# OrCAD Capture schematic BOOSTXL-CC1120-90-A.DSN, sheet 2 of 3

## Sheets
2 CC1190: size B
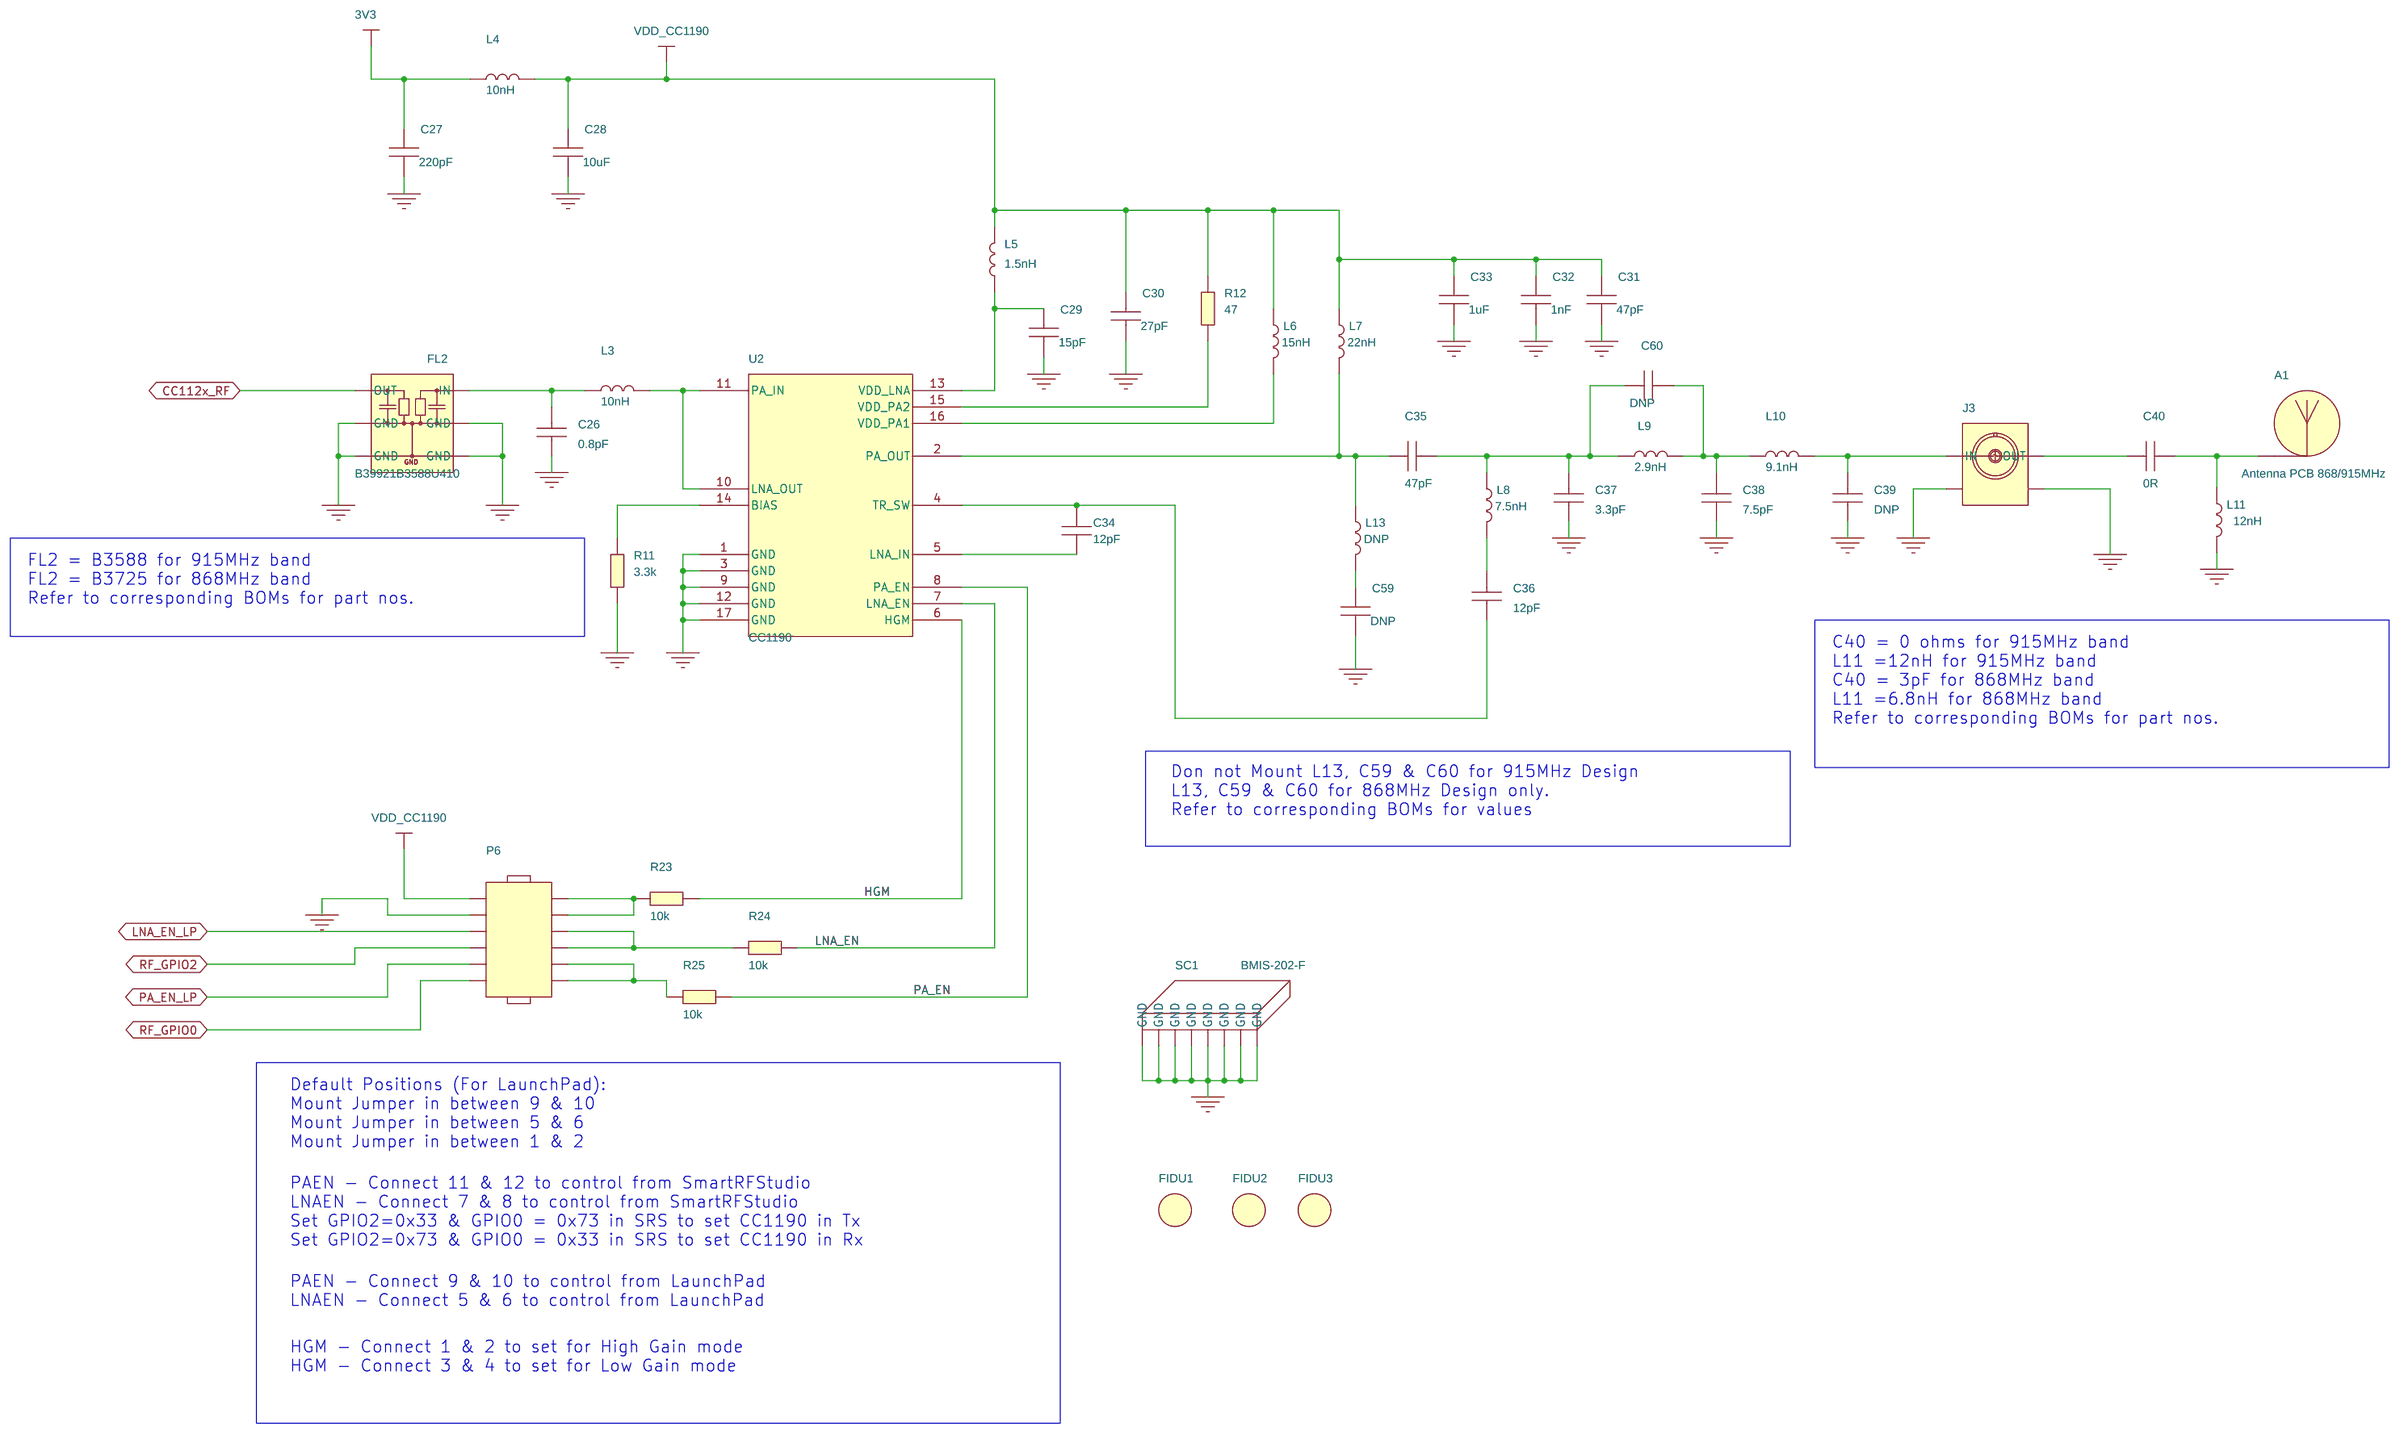
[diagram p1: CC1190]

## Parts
A1  Antenna PCB 868/915MHz  [Antenna868_915MHz_A2N]
C26  0.8pF  [CAPC1005X60N]
C27  220pF  [CAPC1005X60N]
C28  10uF  [CAPC1608X100N]
C29  15pF  [CAPC1005X60N]
C30  27pF  [CAPC1005X60N]
C31  47pF  [CAPC1005X60N]
C32  1nF  [CAPC1005X60N]
C33  1uF  [CAPC1005X60N]
C34  12pF  [CAPC1005X60N]
C35  47pF  [CAPC1005X60N]
C36  12pF  [CAPC1005X60N]
C37  3.3pF  [CAPC1005X60N]
C38  7.5pF  [CAPC1005X60N]
C39  DNP  [CAPC1005X60N]
C40  0R  [CAPC1005X60N]
C59  DNP  [CAPC1005X60N]
C60  DNP  [CAPC1005X60N]
FIDU1  FIDU_1MM  [FID100X115]
FIDU2  FIDU_1MM  [FID100X115]
FIDU3  FIDU_1MM  [FID100X115]
FL2  B39921B3588U410  [FIL_DCC6CN]
J3  1551372-1  [TE_1551372-1_A2N]
L3  10nH  [IND_LQW15AN]
L4  10nH  [IND_LQW15AN]
L5  1.5nH  [INDC1005X60N]
L6  15nH  [IND_LQW15AN]
L7  22nH  [INDC1608X100N]
L8  7.5nH  [IND_LQW15AN]
L9  2.9nH  [IND_LQW15AN]
L10  9.1nH  [INDC1005X60N]
L11  12nH  [IND_LQW15AN]
L13  DNP  [INDC1005X60N]
P6  TSM-106-01-L-DV-P  [SAMTEC_TSM10601LDVPN]
R11  3.3k  [RESC1005X40N]
R12  47  [RESC1005X40N]
R23  10k  [RESC1005X40N]
R24  10k  [RESC1005X40N]
R25  10k  [RESC1005X40N]
SC1  BMIS-202-F  [MECH_BMIS202FN]
U2  CC1190  [QFNFC65P400X400X100-17AN]

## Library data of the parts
A1 = ANTENNA_0: MECHANIC, ANTENNA PCB HELIX 868/915MHz, SMD; AutoDoc File: http://notefied-dynamic-precision.com/DB/Apps/Desktop/Item/Object.aspx?id=87165; Budget Currency: N/A; Budget Price: N/A; Datasheet URL 1: N/A; Datasheet URL 2: www.ti.com; Definied Quality: COMMERCIAL; Esd Level: N/A; FPLIST: Antenna868_915MHz_A2N,Antenna868_915MHz_MIRROR_A2N,; Frequency: 868/915MHz; Last Time Buy: N/A; Lead Time: N/A; MPN: ANTENNA PCB HELIX 868/915MHz; MPN Status: ACTIVE; MSL: N/A; MTBF: N/A; MTBF Standard: N/A; Manufacturer: TEXAS INSTRUMENTS; Max Oper Temp: N/A; Min Oper Temp: N/A; Mounting Type: SMD; NOTE Status: PREFERRED; Old Footprint: Antenna868_915MHz_A2N,Antenna868_915MHz_MIRROR_A2N; Packing Size: 2500; Packing Type: TAPE_&_REEL; Part Number: 13-00397; Part Type: MECHANIC\ANTENNA; Revision: R003; RoHS Status: ROHS_COMPLIANT; WEIGHT: N/A
C26 = CAPACITOR: CAPACITOR, CERAMIC C0G/NP0, 0.8pF, 50V, -0.1pF/+0.1pF, -55DEGC/+125DEGC, 0402, SMD; ALT_SYMBOLS: CAPC1005X60L,CAPC1005X60M; AutoDoc File: http://notefied-dynamic-precision.com/DB/Apps/Desktop/Item/Object.aspx?id=90851; Budget Currency: EUR; Budget Price: 0.014; Datasheet URL 1: http://search.murata.co.jp/Ceramy/image/img/w_hinm/L0005E.pdf; Datasheet URL 2: http://psearch.murata.com/capacitor/product/GRM1555C1HR80BA01%23.pdf; Definied Quality: INDUSTRIAL; Dielectric Type: C0G/NP0; Esd Level: N/A; FPLIST: CAPC1005X60N,CAPC1005X60L,CAPC1005X60M; Last Time Buy: N/A; Lead Time: 12; MPN: GRM1555C1HR80BA01D; MPN Status: ACTIVE; MSL: N/A; MTBF: N/A; MTBF Standard: N/A; Manufacturer: MURATA; Max Oper Temp: +125DEGC; Max TC: +30PPM/DEGC; Max Tol: +0.1pF; Min Oper Temp: -55DEGC; Min TC: -30PPM/DEGC; Min Tol: -0.1pF; Mounting Type: SMD; NOTE Status: PREFERRED; PCB Package: 0402; Packing Size: 10000; Packing Type: TAPE_&_REEL; Part Number: 02-05034; Part Type: CAPACITOR\CERAMIC\0402; Revision: R001; RoHS Status: ROHS_COMPLIANT; Rtd Voltage: 50V; WEIGHT: 0.0016g
C27 = CAPACITOR: CAPACITOR, CERAMIC C0G/NP0, 220pF, 50V, -5%/+5%, -55DEGC/+125DEGC, 0402, SMD; ALT_SYMBOLS: CAPC1005X60L,CAPC1005X60M; AutoDoc File: http://notefied-dynamic-precision.com/DB/Apps/Desktop/Item/Object.aspx?id=50427; Budget Currency: EUR; Budget Price: 0.006; Datasheet URL 1: http://search.murata.co.jp/Ceramy/image/img/w_hinm/L0005E.pdf; Datasheet URL 2: http://psearch.murata.com/capacitor/product/GRM1555C1H221JA01%23.pdf; Definied Quality: INDUSTRIAL; Dielectric Type: C0G/NP0; Esd Level: N/A; FPLIST: CAPC1005X60N,CAPC1005X60L,CAPC1005X60M; Last Time Buy: N/A; Lead Time: 12; LifeCycle Status: GROWTH; MPN: GRM1555C1H221JA01D; MPN Status: ACTIVE; MSL: 1; MTBF: N/A; MTBF Standard: N/A; Manufacturer: MURATA; Max Oper Temp: +125DEGC; Max Tol: +5%; Min Oper Temp: -55DEGC; Min Tol: -5%; Mounting Type: SMD; NOTE Status: PREFERRED; Old Footprint: CAPC1005X60N,0402; PCB Package: 0402; Packing Size: 10000; Packing Type: TAPE_&_REEL; Part Number: 02-01276; Part Type: CAPACITOR\CERAMIC\0402; Revision: R001; RoHS Status: ROHS_COMPLIANT; Rtd Voltage: 50V; WEIGHT: 0.0016g
C28 = CAPACITOR: CAPACITOR, CERAMIC X5R, 10uF, 16V, -20%/+20%, -55DEGC/+85DEGC, 0603, SMD; ALT_SYMBOLS: CAPC1608X100L,CAPC1608X100M; AutoDoc File: http://notefied-dynamic-precision.com/DB/Apps/Desktop/Item/Object.aspx?id=94995; Budget Currency: EUR; Budget Price: 0.12; Datasheet URL 1: N/A; Datasheet URL 2: http://www.yuden.co.jp/eu/product/category/capacitor/EMK107BBJ106MA-T.pdf; Definied Quality: INDUSTRIAL; Dielectric Type: X5R; Esd Level: N/A; FPLIST: CAPC1608X100N,CAPC1608X100L,CAPC1608X100M; Last Time Buy: N/A; Lead Time: 5; MPN: EMK107BBJ106MA-T; MPN Status: ACTIVE; MSL: N/A; MTBF: N/A; MTBF Standard: N/A; Manufacturer: TAIYO YUDEN; Max Oper Temp: +85DEGC; Max Tol: +20%; Min Oper Temp: -55DEGC; Min Tol: -20%; Mounting Type: SMD; NOTE Status: PREFERRED; PCB Package: 0603; Packing Size: 4000; Packing Type: TAPE_&_REEL; Part Number: 02-05939; Part Type: CAPACITOR\CERAMIC\0603; Revision: R001; RoHS Status: ROHS_COMPLIANT; Rtd Voltage: 16V; WEIGHT: N/A
C29 = CAPACITOR: CAPACITOR, CERAMIC C0G/NP0, 15pF, 50V, -5%/+5%, -55DEGC/+125DEGC, 0402, SMD; ALT_SYMBOLS: CAPC1005X60L,CAPC1005X60M; AutoDoc File: http://notefied-dynamic-precision.com/DB/Apps/Desktop/Item/Object.aspx?id=87791; Budget Currency: EUR; Budget Price: 0.005; Datasheet URL 1: http://search.murata.co.jp/Ceramy/image/img/w_hinm/L0005E.pdf; Datasheet URL 2: http://psearch.murata.com/capacitor/product/GRM1555C1H150JA01%23.pdf; Definied Quality: INDUSTRIAL; Dielectric Type: C0G/NP0; Esd Level: N/A; FPLIST: CAPC1005X60N,CAPC1005X60L,CAPC1005X60M; Last Time Buy: N/A; Lead Time: 12; MPN: GRM1555C1H150JA01D; MPN Status: ACTIVE; MSL: 1; MTBF: N/A; MTBF Standard: N/A; Manufacturer: MURATA; Max Oper Temp: +125DEGC; Max TC: +30PPM/DEGC; Max Tol: +5%; Min Oper Temp: -55DEGC; Min TC: -30PPM/DEGC; Min Tol: -5%; Mounting Type: SMD; NOTE Status: PREFERRED; PCB Package: 0402; Packing Size: 10000; Packing Type: TAPE_&_REEL; Part Number: 02-04673; Part Type: CAPACITOR\CERAMIC\0402; Revision: R001; RoHS Status: ROHS_COMPLIANT; Rtd Voltage: 50V; WEIGHT: 0.0016g
C30 = CAPACITOR: CAPACITOR, CERAMIC C0G/NP0, 27pF, 50V, -5%/+5%, -55DEGC/+125DEGC, 0402, SMD; ALT_SYMBOLS: CAPC1005X60L,CAPC1005X60M; AutoDoc File: http://notefied-dynamic-precision.com/DB/Apps/Desktop/Item/Object.aspx?id=90599; Budget Currency: EUR; Budget Price: 0.005; Datasheet URL 1: http://search.murata.co.jp/Ceramy/image/img/w_hinm/L0005E.pdf; Datasheet URL 2: http://psearch.murata.com/capacitor/product/GRM1555C1H270JA01%23.pdf; Definied Quality: INDUSTRIAL; Dielectric Type: C0G/NP0; Esd Level: N/A; FPLIST: CAPC1005X60N,CAPC1005X60L,CAPC1005X60M; Last Time Buy: N/A; Lead Time: 12; MPN: GRM1555C1H270JA01D; MPN Status: ACTIVE; MSL: N/A; MTBF: N/A; MTBF Standard: N/A; Manufacturer: MURATA; Max Oper Temp: +125DEGC; Max Tol: +5%; Min Oper Temp: -55DEGC; Min Tol: -5%; Mounting Type: SMD; NOTE Status: PREFERRED; PCB Package: 0402; Packing Size: 10000; Packing Type: TAPE_&_REEL; Part Number: 02-05017; Part Type: CAPACITOR\CERAMIC\0402; Revision: R001; RoHS Status: ROHS_COMPLIANT; Rtd Voltage: 50V; WEIGHT: 0.0016g
C31 C35 = CAPACITOR: CAPACITOR, CERAMIC C0G/NP0, 47pF, 50V, -5%/+5%, -55DEGC/+125DEGC, 0402, SMD; ALT_SYMBOLS: CAPC1005X60L,CAPC1005X60M; AutoDoc File: http://notefied-dynamic-precision.com/DB/Apps/Desktop/Item/Object.aspx?id=86073; Budget Currency: EUR; Budget Price: 0.006; Datasheet URL 1: http://search.murata.co.jp/Ceramy/image/img/w_hinm/L0005E.pdf; Datasheet URL 2: http://psearch.murata.com/capacitor/product/GRM1555C1H470JA01%23.pdf; Definied Quality: INDUSTRIAL; Dielectric Type: C0G/NP0; Esd Level: N/A; FPLIST: CAPC1005X60N,CAPC1005X60L,CAPC1005X60M; Last Time Buy: N/A; Lead Time: 12; MPN: GRM1555C1H470JA01D; MPN Status: ACTIVE; MSL: 1; MTBF: N/A; MTBF Standard: N/A; Manufacturer: MURATA; Max Oper Temp: +125DEGC; Max TC: +30PPM/DEGC; Max Tol: +5%; Min Oper Temp: -55DEGC; Min TC: -30PPM/DEGC; Min Tol: -5%; Mounting Type: SMD; NOTE Status: PREFERRED; PCB Package: 0402; Packing Size: 10000; Packing Type: TAPE_&_REEL; Part Number: 02-04366; Part Type: CAPACITOR\CERAMIC\0402; Revision: R001; RoHS Status: ROHS_COMPLIANT; Rtd Voltage: 50V; WEIGHT: 0.0016g
C32 = CAPACITOR: CAPACITOR, CERAMIC X7R, 1nF, 50V, -10%/+10%, -55DEGC/+125DEGC, 0402, SMD; ALT_SYMBOLS: CAPC1005X60L,CAPC1005X60M; AutoDoc File: http://notefied-dynamic-precision.com/DB/Apps/Desktop/Item/Object.aspx?id=72148; Budget Currency: EUR; Budget Price: 0.003; Datasheet URL 1: http://search.murata.co.jp/Ceramy/image/img/w_hinm/L0005E.pdf; Datasheet URL 2: http://psearch.murata.com/capacitor/product/GRM155R71H102KA01%23.pdf; Definied Quality: INDUSTRIAL; Dielectric Type: X7R; Esd Level: N/A; FPLIST: CAPC1005X60N,CAPC1005X60L,CAPC1005X60M; Last Time Buy: N/A; Lead Time: 10; LifeCycle Status: GROWTH; MPN: GRM155R71H102KA01D; MPN Status: ACTIVE; MSL: 1; MTBF: N/A; MTBF Standard: N/A; Manufacturer: MURATA; Max Oper Temp: +125DEGC; Max Tol: +10%; Min Oper Temp: -55DEGC; Min Tol: -10%; Mounting Type: SMD; NOTE Status: PREFERRED; Old Footprint: CAPC1005X60N,0402; PCB Package: 0402; Packing Size: 10000; Packing Type: TAPE_&_REEL; Part Number: 02-02070; Part Type: CAPACITOR\CERAMIC\0402; Revision: R000; RoHS Status: ROHS_COMPLIANT; Rtd Voltage: 50V; WEIGHT: 0.0016g
C33 = CAPACITOR: CAPACITOR, CERAMIC X5R, 1uF, 10V, -10%/+10%, -55DEGC/+85DEGC, 0402, SMD; ALT_SYMBOLS: CAPC1005X60L,CAPC1005X60M; AutoDoc File: http://notefied-dynamic-precision.com/DB/Apps/Desktop/Item/Object.aspx?id=74236; Budget Currency: EUR; Budget Price: 0.015; Datasheet URL 1: http://search.murata.co.jp/Ceramy/image/img/w_hinm/L0005E.pdf; Datasheet URL 2: http://psearch.murata.com/capacitor/product/GRM155R61A105KE15%23.pdf; Definied Quality: INDUSTRIAL; Dielectric Type: X5R; Esd Level: N/A; FPLIST: CAPC1005X60N,CAPC1005X60L,CAPC1005X60M; Last Time Buy: N/A; Lead Time: 14; MPN: GRM155R61A105KE15D; MPN Status: NRND; MSL: 1; MTBF: N/A; MTBF Standard: N/A; Manufacturer: MURATA; Max Oper Temp: +85DEGC; Max Tol: +10%; Min Oper Temp: -55DEGC; Min Tol: -10%; Mounting Type: SMD; NOTE Status: PREFERRED; Old Footprint: CAPC1005X60N,0402; PCB Package: 0402; Packing Size: 10000; Packing Type: TAPE_&_REEL; Part Number: 02-02381; Part Type: CAPACITOR\CERAMIC\0402; Revision: R005; RoHS Status: ROHS_COMPLIANT; Rtd Voltage: 10V; WEIGHT: 0.0016g
C34 C36 = CAPACITOR: CAPACITOR, CERAMIC C0G/NP0, 12pF, 50V, -5%/+5%, -55DEGC/+125DEGC, 0402, SMD; ALT_SYMBOLS: CAPC1005X60L,CAPC1005X60M; AutoDoc File: http://notefied-dynamic-precision.com/DB/Apps/Desktop/Item/Object.aspx?id=84867; Budget Currency: EUR; Budget Price: 0.006; Datasheet URL 1: http://search.murata.co.jp/Ceramy/image/img/w_hinm/L0005E.pdf; Datasheet URL 2: http://psearch.murata.com/capacitor/product/GRM1555C1H120JA01%23.pdf; Definied Quality: INDUSTRIAL; Dielectric Type: C0G/NP0; Esd Level: N/A; FPLIST: CAPC1005X60N,CAPC1005X60L,CAPC1005X60M; Last Time Buy: N/A; Lead Time: 12; MPN: GRM1555C1H120JA01D; MPN Status: ACTIVE; MSL: 1; MTBF: N/A; MTBF Standard: N/A; Manufacturer: MURATA; Max Oper Temp: +125DEGC; Max TC: +30PPM/DEGC; Max Tol: +5%; Min Oper Temp: -55DEGC; Min TC: -30PPM/DEGC; Min Tol: -5%; Mounting Type: SMD; NOTE Status: PREFERRED; PCB Package: 0402; Packing Size: 10000; Packing Type: TAPE_&_REEL; Part Number: 02-04168; Part Type: CAPACITOR\CERAMIC\0402; Revision: R000; RoHS Status: ROHS_COMPLIANT; Rtd Voltage: 50V; WEIGHT: 0.0016g
C37 = CAPACITOR: CAPACITOR, CERAMIC C0G/NP0, 3.3pF, 50V, -0.25pF/+0.25pF, -55DEGC/+125DEGC, 0402, SMD; ALT_SYMBOLS: CAPC1005X60L,CAPC1005X60M; AutoDoc File: http://notefied-dynamic-precision.com/DB/Apps/Desktop/Item/Object.aspx?id=86077; Budget Currency: EUR; Budget Price: 0.006; Datasheet URL 1: http://search.murata.co.jp/Ceramy/image/img/w_hinm/L0005E.pdf; Datasheet URL 2: http://psearch.murata.com/capacitor/product/GRM1555C1H3R3CA01%23.pdf; Definied Quality: INDUSTRIAL; Dielectric Type: C0G/NP0; Esd Level: N/A; FPLIST: CAPC1005X60N,CAPC1005X60L,CAPC1005X60M; Last Time Buy: N/A; Lead Time: 12; MPN: GRM1555C1H3R3CA01D; MPN Status: ACTIVE; MSL: 1; MTBF: N/A; MTBF Standard: N/A; Manufacturer: MURATA; Max Oper Temp: +125DEGC; Max TC: +30PPM/DEGC; Max Tol: +0.25pF; Min Oper Temp: -55DEGC; Min TC: -30PPM/DEGC; Min Tol: -0.25pF; Mounting Type: SMD; NOTE Status: PREFERRED; PCB Package: 0402; Packing Size: 10000; Packing Type: TAPE_&_REEL; Part Number: 02-04369; Part Type: CAPACITOR\CERAMIC\0402; Revision: R001; RoHS Status: ROHS_COMPLIANT; Rtd Voltage: 50V; WEIGHT: 0.0016g
C38 = CAPACITOR: CAPACITOR, CERAMIC C0G/NP0, 7.5pF, 50V, -0.25pF/+0.25pF, -55DEGC/+125DEGC, 0402, SMD; ALT_SYMBOLS: CAPC1005X60L,CAPC1005X60M; AutoDoc File: http://notefied-dynamic-precision.com/DB/Apps/Desktop/Item/Object.aspx?id=90841; Budget Currency: EUR; Budget Price: 0.006; Datasheet URL 1: http://search.murata.co.jp/Ceramy/image/img/w_hinm/L0005E.pdf; Datasheet URL 2: http://psearch.murata.com/capacitor/product/GRM1555C1H7R5CA01%23.pdf; Definied Quality: INDUSTRIAL; Dielectric Type: C0G/NP0; Esd Level: N/A; FPLIST: CAPC1005X60N,CAPC1005X60L,CAPC1005X60M; Last Time Buy: N/A; Lead Time: 10; MPN: GRM1555C1H7R5CA01D; MPN Status: ACTIVE; MSL: N/A; MTBF: N/A; MTBF Standard: N/A; Manufacturer: MURATA; Max Oper Temp: +125DEGC; Max TC: +30PPM/DEGC; Max Tol: +0.25pF; Min Oper Temp: -55DEGC; Min TC: -30PPM/DEGC; Min Tol: -0.25pF; Mounting Type: SMD; NOTE Status: PREFERRED; PCB Package: 0402; Packing Size: 10000; Packing Type: TAPE_&_REEL; Part Number: 02-05033; Part Type: CAPACITOR\CERAMIC\0402; Revision: R001; RoHS Status: ROHS_COMPLIANT; Rtd Voltage: 50V; WEIGHT: 0.0016g
C39 = CAPACITOR: CAPACITOR, CERAMIC C0G/NP0, 7.5pF, 50V, -0.25pF/+0.25pF, -55DEGC/+125DEGC, 0402, SMD; ALT_SYMBOLS: CAPC1005X60L,CAPC1005X60M; AutoDoc File: http://notefied-dynamic-precision.com/DB/Apps/Desktop/Item/Object.aspx?id=90841; Budget Currency: EUR; Budget Price: 0.006; Capacitance: 7.5pF; Datasheet URL 1: http://search.murata.co.jp/Ceramy/image/img/w_hinm/L0005E.pdf; Datasheet URL 2: http://psearch.murata.com/capacitor/product/GRM1555C1H7R5CA01%23.pdf; Definied Quality: INDUSTRIAL; Dielectric Type: C0G/NP0; Esd Level: N/A; FPLIST: CAPC1005X60N,CAPC1005X60L,CAPC1005X60M; Last Time Buy: N/A; Lead Time: 10; MPN: GRM1555C1H7R5CA01D; MPN Status: ACTIVE; MSL: N/A; MTBF: N/A; MTBF Standard: N/A; Manufacturer: MURATA; Max Oper Temp: +125DEGC; Max TC: +30PPM/DEGC; Max Tol: +0.25pF; Min Oper Temp: -55DEGC; Min TC: -30PPM/DEGC; Min Tol: -0.25pF; Mounting Type: SMD; NOTE Status: PREFERRED; PCB Package: 0402; Packing Size: 10000; Packing Type: TAPE_&_REEL; Part Number: 02-05033; Part Type: CAPACITOR\CERAMIC\0402; Revision: R001; RoHS Status: ROHS_COMPLIANT; Rtd Voltage: 50V; WEIGHT: 0.0016g
C40 = CAPACITOR: CAPACITOR, CERAMIC C0G/NP0, 1pF, 50V, -0.1pF/+0.1pF, -55DEGC/+125DEGC, 0402, SMD; ALT_SYMBOLS: CAPC1005X60L,CAPC1005X60M; AutoDoc File: http://notefied-dynamic-precision.com/DB/Apps/Desktop/Item/Object.aspx?id=86074; Budget Currency: EUR; Budget Price: 0.009; Capacitance: 1pF; Datasheet URL 1: http://search.murata.co.jp/Ceramy/image/img/w_hinm/L0005E.pdf; Datasheet URL 2: http://psearch.murata.com/capacitor/product/GRM1555C1H1R0BA01%23.pdf; Definied Quality: INDUSTRIAL; Dielectric Type: C0G/NP0; Esd Level: N/A; FPLIST: CAPC1005X60N,CAPC1005X60L,CAPC1005X60M; Last Time Buy: N/A; Lead Time: 12; MPN: GRM1555C1H1R0BA01D; MPN Status: ACTIVE; MSL: 1; MTBF: N/A; MTBF Standard: N/A; Manufacturer: MURATA; Max Oper Temp: +125DEGC; Max TC: +30PPM/DEGC; Max Tol: +0.1pF; Min Oper Temp: -55DEGC; Min TC: -30PPM/DEGC; Min Tol: -0.1pF; Mounting Type: SMD; NOTE Status: PREFERRED; PCB Package: 0402; Packing Size: 10000; Packing Type: TAPE_&_REEL; Part Number: 02-04367; Part Type: CAPACITOR\CERAMIC\0402; Revision: R001; RoHS Status: ROHS_COMPLIANT; Rtd Voltage: 50V; WEIGHT: 0.0016g
C59 = CAPACITOR: CAPACITOR, CERAMIC C0G/NP0, 2.7pF, 50V, -0.25pF/+0.25pF, -55DEGC/+125DEGC, 0402, SMD; ALT_SYMBOLS: CAPC1005X60L,CAPC1005X60M; AutoDoc File: http://notefied-dynamic-precision.com/DB/Apps/Desktop/Item/Object.aspx?id=87809; Budget Currency: EUR; Budget Price: 0.006; Capacitance: 2.7pF; Datasheet URL 1: http://search.murata.co.jp/Ceramy/image/img/w_hinm/L0005E.pdf; Datasheet URL 2: http://psearch.murata.com/capacitor/product/GRM1555C1H2R7CA01%23.pdf; Definied Quality: INDUSTRIAL; Dielectric Type: C0G/NP0; Esd Level: N/A; FPLIST: CAPC1005X60N,CAPC1005X60L,CAPC1005X60M; Last Time Buy: N/A; Lead Time: 12; MPN: GRM1555C1H2R7CA01D; MPN Status: ACTIVE; MSL: 1; MTBF: N/A; MTBF Standard: N/A; Manufacturer: MURATA; Max Oper Temp: +125DEGC; Max Tol: +0.25pF; Min Oper Temp: -55DEGC; Min Tol: -0.25pF; Mounting Type: SMD; NOTE Status: PREFERRED; PCB Package: 0402; Packing Size: 10000; Packing Type: TAPE_&_REEL; Part Number: 02-04679; Part Type: CAPACITOR\CERAMIC\0402; Revision: R001; RoHS Status: ROHS_COMPLIANT; Rtd Voltage: 50V; WEIGHT: 0.0016g
C60 = CAPACITOR: CAPACITOR, CERAMIC C0G/NP0, 2.4pF, 50V, -0.25pF/+0.25pF, -55DEGC/+125DEGC, 0402, SMD; ALT_SYMBOLS: CAPC1005X60L,CAPC1005X60M; AutoDoc File: http://notefied-dynamic-precision.com/DB/Apps/Desktop/Item/Object.aspx?id=87374; Budget Currency: EUR; Budget Price: 0.006; Capacitance: 2.4pF; Datasheet URL 1: http://search.murata.co.jp/Ceramy/image/img/w_hinm/L0005E.pdf; Datasheet URL 2: http://psearch.murata.com/capacitor/product/GRM1555C1H2R4CA01%23.pdf; Definied Quality: INDUSTRIAL; Dielectric Type: C0G/NP0; Esd Level: N/A; FPLIST: CAPC1005X60N,CAPC1005X60L,CAPC1005X60M; Last Time Buy: N/A; Lead Time: 10; MPN: GRM1555C1H2R4CA01D; MPN Status: ACTIVE; MSL: 1; MTBF: N/A; MTBF Standard: N/A; Manufacturer: MURATA; Max Oper Temp: +125DEGC; Max TC: +30PPM/DEGC; Max Tol: +0.25pF; Min Oper Temp: -55DEGC; Min TC: -30PPM/DEGC; Min Tol: -0.25pF; Mounting Type: SMD; NOTE Status: PREFERRED; PCB Package: 0402; Packing Size: 10000; Packing Type: TAPE_&_REEL; Part Number: 02-04632; Part Type: CAPACITOR\CERAMIC\0402; Revision: R001; RoHS Status: ROHS_COMPLIANT; Rtd Voltage: 50V; WEIGHT: 0.0016g
FIDU1-FIDU3 = FIDMARK: FIDUCIAL MARK, ROUND 1MM; AutoDoc File: http://notefied-dynamic-precision.com/DB/Apps/Desktop/Item/Object.aspx?id=74548; Part Number: 19-00111; Part Type: NON_COMPONENT\FIDUCIAL; Revision: R001
FL2 = FILTER_SAW_RF_B3588: FILTER, SAW, 50@915MHz, -45DEGC/+125DEGC, DCC6C, SMD; ALT_SYMBOLS: FIL_DCC6CL,FIL_DCC6CM; AutoDoc File: http://notefied-dynamic-precision.com/DB/Apps/Desktop/Item/Object.aspx?id=89130; Budget Currency: USD; Budget Price: 0.9917; Datasheet URL 1: N/A; Datasheet URL 2: http://www.epcos.com/inf/40/ds/ae/B3588.pdf; FPLIST: FIL_DCC6CN,FIL_DCC6CL,FIL_DCC6CM; Frequency: 915MHz; Impedance: 50; MPN Status: ACTIVE; Manufacturer: TDK-EPCOS; Max Oper Temp: +85DEGC; Min Oper Temp: -45DEGC; Mounting Type: SMD; NOTE Status: PREFERRED; PCB Package: DCC6C; Part Number: 04-00530; Part Type: FILTER\EMI\OTHER_SMD; Revision: R001; RoHS Status: ROHS_COMPLIANT; Rtd Voltage: 5V
J3 = CONN_COAX_1551372-1: CONNECTOR, COAX, RF, STRAIGHT, PICO SWITCHING COAX CONNECTOR, UP TO 11GHz, SMD; ALT_SYMBOLS: TE_1551372-1_A2L,TE_1551372-1_A2M; AutoDoc File: http://notefied-dynamic-precision.com/DB/Apps/Desktop/Item/Object.aspx?id=103803; Datasheet URL 1: http://www.te.com/commerce/DocumentDelivery/DDEController?Action=showdoc&DocId=Customer+Drawing%7F1551372%7FA6%7Fpdf%7FEnglish%7FENG_CD_1551372_A6.pdf%7F1551372-1; Datasheet URL 2: http://www.te.com/commerce/DocumentDelivery/DDEController?Action=showdoc&DocId=Specification+Or+Standard%7F108-19355%7FC1%7Fpdf%7FEnglish%7FENG_SS_108-19355_C1.pdf%7F1551372-1; FPLIST: TE_1551372-1_A2N,TE_1551372-1_A2L,TE_1551372-1_A2M; Frequency: UP TO 11GHz; Impedance: 50; MPN Status: ACTIVE; Manufacturer: TE CONNECTIVITY; Max Oper Temp: +85DEGC; Min Oper Temp: -40DEGC; Mounting Type: SMD; NOTE Status: PREFERRED; Packing Size: 10000; Packing Type: TAPE_&_REEL; Part Number: 06-04877; Part Type: CONNECTOR\COAX; Revision: R001; RoHS Status: ROHS_COMPLIANT; Rtd Power: 2W; Rtd Voltage: 250V
L3 = INDUCTOR_4: INDUCTOR, CHIP, 10nH, -5%/+5%, 0.5A, -55DEGC/+125DEGC, 0402, SMD; ALT_SYMBOLS: IND_LQW15AM,IND_LQW15AL; AutoDoc File: http://notefied-dynamic-precision.com/DB/Apps/Desktop/Item/Object.aspx?id=86082; Budget Currency: EUR; Budget Price: 0.117; Datasheet URL 1: N/A; Datasheet URL 2: http://psearch.murata.com/inductor/product/LQW15AN10NJ00%23.pdf; Definied Quality: INDUSTRIAL; Esd Level: N/A; FPLIST: IND_LQW15AN,IND_LQW15AM,IND_LQW15AL; Frequency: 5.5GHz; Last Time Buy: N/A; Lead Time: 9; MPN: LQW15AN10NJ00D; MPN Status: NRND; MSL: N/A; MTBF: N/A; MTBF Standard: N/A; Manufacturer: MURATA; Max Oper Temp: +125DEGC; Max Tol: +5%; Min Oper Temp: -55DEGC; Min Tol: -5%; Mounting Type: SMD; NOTE Status: PREFERRED; PCB Package: 0402; Packing Size: 10000; Packing Type: TAPE_&_REEL; Part Number: 03-06552; Part Type: INDUCTOR\CHIP\0402; Resistance: 0.17; Revision: R001; RoHS Status: ROHS_COMPLIANT; Rtd Current: 0.5A; WEIGHT: 0.0008g
L4 = INDUCTOR_1: INDUCTOR, CHIP, 10nH, -5%/+5%, 0.5A, -55DEGC/+125DEGC, 0402, SMD; ALT_SYMBOLS: IND_LQW15AM,IND_LQW15AL; AutoDoc File: http://notefied-dynamic-precision.com/DB/Apps/Desktop/Item/Object.aspx?id=86082; Budget Currency: EUR; Budget Price: 0.117; Datasheet URL 1: N/A; Datasheet URL 2: http://psearch.murata.com/inductor/product/LQW15AN10NJ00%23.pdf; Definied Quality: INDUSTRIAL; Esd Level: N/A; FPLIST: IND_LQW15AN,IND_LQW15AM,IND_LQW15AL; Frequency: 5.5GHz; Last Time Buy: N/A; Lead Time: 9; MPN: LQW15AN10NJ00D; MPN Status: NRND; MSL: N/A; MTBF: N/A; MTBF Standard: N/A; Manufacturer: MURATA; Max Oper Temp: +125DEGC; Max Tol: +5%; Min Oper Temp: -55DEGC; Min Tol: -5%; Mounting Type: SMD; NOTE Status: PREFERRED; PCB Package: 0402; Packing Size: 10000; Packing Type: TAPE_&_REEL; Part Number: 03-06552; Part Type: INDUCTOR\CHIP\0402; Resistance: 0.17; Revision: R001; RoHS Status: ROHS_COMPLIANT; Rtd Current: 0.5A; WEIGHT: 0.0008g
L5 = INDUCTOR_5: INDUCTOR, CHIP, 1.5nH, -0.3nH/ +0.3nH, 0.3A, -55DEGC/+125DEGC, 0402, SMD; ALT_SYMBOLS: INDC1005X60L,INDC1005X60M; AutoDoc File: http://notefied-dynamic-precision.com/DB/Apps/Desktop/Item/Object.aspx?id=87446; Budget Currency: EUR; Budget Price: 0.024; Datasheet URL 1: N/A; Datasheet URL 2: http://psearch.murata.com/inductor/product/LQG15HS1N5S02%23.pdf; Definied Quality: INDUSTRIAL; Esd Level: N/A; FPLIST: INDC1005X60N,INDC1005X60L,INDC1005X60M; Frequency: 6GHz; Last Time Buy: N/A; Lead Time: 9; MPN: LQG15HS1N5S02D; MPN Status: NRND; MSL: N/A; MTBF: N/A; MTBF Standard: N/A; Manufacturer: MURATA; Max Oper Temp: +125DEGC; Max Tol: +0.3nH; Min Oper Temp: -55DEGC; Min Tol: -0.3nH; Mounting Type: SMD; NOTE Status: PREFERRED; PCB Package: 0402; Packing Size: 10000; Packing Type: TAPE_&_REEL; Part Number: 03-06609; Part Type: INDUCTOR\CHIP\0402; Resistance: 0.1; Revision: R001; RoHS Status: ROHS_COMPLIANT; Rtd Current: 0.3A; WEIGHT: 0.001g
L6 = INDUCTOR_6: INDUCTOR, CHIP, 15nH, -5%/+5%, 0.46A, -55DEGC/+125DEGC, 0402, SMD; ALT_SYMBOLS: IND_LQW15AM,IND_LQW15AL; AutoDoc File: http://notefied-dynamic-precision.com/DB/Apps/Desktop/Item/Object.aspx?id=86087; Budget Currency: EUR; Budget Price: 0.117; Datasheet URL 1: N/A; Datasheet URL 2: http://psearch.murata.com/inductor/product/LQW15AN15NJ00%23.pdf; Definied Quality: INDUSTRIAL; Esd Level: N/A; FPLIST: IND_LQW15AN,IND_LQW15AM,IND_LQW15AL; Frequency: 5GHz; Last Time Buy: N/A; Lead Time: 9; MPN: LQW15AN15NJ00D; MPN Status: NRND; MSL: N/A; MTBF: N/A; MTBF Standard: N/A; Manufacturer: MURATA; Max Oper Temp: +125DEGC; Max Tol: +5%; Min Oper Temp: -55DEGC; Min Tol: -5%; Mounting Type: SMD; NOTE Status: PREFERRED; PCB Package: 0402; Packing Size: 10000; Packing Type: TAPE_&_REEL; Part Number: 03-06555; Part Type: INDUCTOR\CHIP\0402; Resistance: 0.16; Revision: R001; RoHS Status: ROHS_COMPLIANT; Rtd Current: 0.46A; WEIGHT: 0.0008g
L7 = INDUCTOR_7: INDUCTOR, CHIP, 22nH, -5%/+5%, -55DEGC/+125DEGC, 0603, SMD; ALT_SYMBOLS: INDC1608X100L,INDC1608X100M; AutoDoc File: http://notefied-dynamic-precision.com/DB/Apps/Desktop/Item/Object.aspx?id=90768; Budget Currency: EUR; Budget Price: 0.126; Datasheet URL 1: N/A; Datasheet URL 2: http://psearch.murata.com/inductor/product/LQW18AN22NJ10%23.pdf; Definied Quality: INDUSTRIAL; Esd Level: N/A; FPLIST: INDC1608X100N,INDC1608X100L,INDC1608X100M; Frequency: 3.2GHz; Last Time Buy: N/A; Lead Time: 7; MPN: LQW18AN22NJ10D; MPN Status: NRND; MSL: N/A; MTBF: N/A; MTBF Standard: N/A; Manufacturer: MURATA; Max Oper Temp: +125DEGC; Max Tol: +5%; Min Oper Temp: -55DEGC; Min Tol: -5%; Mounting Type: SMD; NOTE Status: PREFERRED; PCB Package: 0603; Packing Size: 4000; Packing Type: TAPE_&_REEL; Part Number: 03-06783; Part Type: INDUCTOR\CHIP\0603; Resistance: 0.099; Revision: R001; RoHS Status: ROHS_COMPLIANT; Rtd Current: 0.64A; WEIGHT: 0.003g
L8 = INDUCTOR_9: INDUCTOR, CHIP, 7.5nH, -2%/+2%, 0.57A, -55DEGC/+125DEGC, 0402, SMD; ALT_SYMBOLS: IND_LQW15AM,IND_LQW15AL; AutoDoc File: http://notefied-dynamic-precision.com/DB/Apps/Desktop/Item/Object.aspx?id=86081; Budget Currency: EUR; Budget Price: 0.128; Datasheet URL 1: N/A; Datasheet URL 2: http://psearch.murata.com/inductor/product/LQW15AN7N5G00%23.pdf; Definied Quality: INDUSTRIAL; Esd Level: N/A; FPLIST: IND_LQW15AN,IND_LQW15AM,IND_LQW15AL; Frequency: 6GHz; Last Time Buy: N/A; Lead Time: 9; MPN: LQW15AN7N5G00D; MPN Status: NRND; MSL: N/A; MTBF: N/A; MTBF Standard: N/A; Manufacturer: MURATA; Max Oper Temp: +125DEGC; Max Tol: +2%; Min Oper Temp: -55DEGC; Min Tol: -2%; Mounting Type: SMD; NOTE Status: PREFERRED; PCB Package: 0402; Packing Size: 10000; Packing Type: TAPE_&_REEL; Part Number: 03-06551; Part Type: INDUCTOR\CHIP\0402; Resistance: 0.13; Revision: R001; RoHS Status: ROHS_COMPLIANT; Rtd Current: 0.57A; WEIGHT: 0.0008g
L9 = INDUCTOR_0: INDUCTOR, CHIP, 2.9nH, -0.2nH/+0.2nH, 0.75A, -55DEGC/+125DEGC, 0402, SMD; ALT_SYMBOLS: IND_LQW15AM,IND_LQW15AL; AutoDoc File: http://notefied-dynamic-precision.com/DB/Apps/Desktop/Item/Object.aspx?id=88047; Budget Currency: EUR; Budget Price: 0.123; Datasheet URL 1: N/A; Datasheet URL 2: http://psearch.murata.com/inductor/product/LQW15AN2N9C00%23.pdf; Definied Quality: INDUSTRIAL; Esd Level: N/A; FPLIST: IND_LQW15AN,IND_LQW15AM,IND_LQW15AL; Frequency: 15GHz; Last Time Buy: N/A; Lead Time: 7; MPN: LQW15AN2N9C00D; MPN Status: NRND; MSL: N/A; MTBF: N/A; MTBF Standard: N/A; Manufacturer: MURATA; Max Oper Temp: +125DEGC; Max Tol: +0.2nH; Min Oper Temp: -55DEGC; Min Tol: -0.2nH; Mounting Type: SMD; NOTE Status: PREFERRED; PCB Package: 0402; Packing Size: 10000; Packing Type: TAPE_&_REEL; Part Number: 03-06655; Part Type: INDUCTOR\CHIP\0402; Resistance: 0.07; Revision: R001; RoHS Status: ROHS_COMPLIANT; Rtd Current: 0.75A; WEIGHT: 0.0008g
L10 = INDUCTOR_10: INDUCTOR, CHIP, 9.1nH, -2%/+2%, 0.54A, -55DEGC/+125DEGC, 0402, SMD; ALT_SYMBOLS: INDC1005X60L,INDC1005X60M; AutoDoc File: http://notefied-dynamic-precision.com/DB/Apps/Desktop/Item/Object.aspx?id=90847; Budget Currency: EUR; Budget Price: 0.128; Datasheet URL 1: N/A; Datasheet URL 2: http://psearch.murata.com/inductor/product/LQW15AN9N1G00%23.pdf; Definied Quality: INDUSTRIAL; Esd Level: N/A; FPLIST: INDC1005X60N,INDC1005X60L,INDC1005X60M; Frequency: 5.5GHz; Last Time Buy: N/A; Lead Time: 7; MPN: LQW15AN9N1G00D; MPN Status: NRND; MSL: N/A; MTBF: N/A; MTBF Standard: N/A; Manufacturer: MURATA; Max Oper Temp: +125DEGC; Max Tol: +2%; Min Oper Temp: -55DEGC; Min Tol: -2%; Mounting Type: SMD; NOTE Status: PREFERRED; PCB Package: 0402; Packing Size: 10000; Packing Type: TAPE_&_REEL; Part Number: 03-06784; Part Type: INDUCTOR\CHIP\0402; Resistance: 0.14; Revision: R001; RoHS Status: ROHS_COMPLIANT; Rtd Current: 0.54A; WEIGHT: 0.0008g
L11 = INDUCTOR_11: INDUCTOR, CHIP, 12nH, -5%/+5%, 0.5A, -55DEGC/+125DEGC, 0402, SMD; ALT_SYMBOLS: IND_LQW15AM,IND_LQW15AL; AutoDoc File: http://notefied-dynamic-precision.com/DB/Apps/Desktop/Item/Object.aspx?id=86088; Budget Currency: EUR; Budget Price: 0.117; Datasheet URL 1: N/A; Datasheet URL 2: http://psearch.murata.com/inductor/product/LQW15AN12NJ00%23.pdf; Definied Quality: INDUSTRIAL; Esd Level: N/A; FPLIST: IND_LQW15AN,IND_LQW15AM,IND_LQW15AL; Frequency: 5.5GHz; Last Time Buy: N/A; Lead Time: 9; MPN: LQW15AN12NJ00D; MPN Status: NRND; MSL: N/A; MTBF: N/A; MTBF Standard: N/A; Manufacturer: MURATA; Max Oper Temp: +125DEGC; Max Tol: +5%; Min Oper Temp: -55DEGC; Min Tol: -5%; Mounting Type: SMD; NOTE Status: PREFERRED; PCB Package: 0402; Packing Size: 10000; Packing Type: TAPE_&_REEL; Part Number: 03-06556; Part Type: INDUCTOR\CHIP\0402; Resistance: 0.14; Revision: R001; RoHS Status: ROHS_COMPLIANT; Rtd Current: 0.5A; WEIGHT: 0.0008g
L13 = INDUCTOR_8: INDUCTIVE, CHIP COIL, 2.7nH, -0.3nH/+0.3nH, 0.3A, 6000MHz, 0402, SMD; ALT_SYMBOLS: INDC1005X60L,INDC1005X60M; AutoDoc File: http://notefied-dynamic-precision.com/DB/Apps/Desktop/Item/Object.aspx?id=74524; Budget Currency: EUR; Budget Price: 0.024; Datasheet URL 1: N/A; Datasheet URL 2: http://psearch.murata.com/inductor/product/LQG15HS2N7S02%23.pdf; Definied Quality: INDUSTRIAL; Esd Level: N/A; FPLIST: INDC1005X60N,INDC1005X60L,INDC1005X60M; Inductance: 2.7nH; Last Time Buy: N/A; Lead Time: 9; MPN: LQG15HS2N7S02D; MPN Status: NRND; MSL: N/A; MTBF: N/A; MTBF Standard: N/A; Manufacturer: MURATA; Max Oper Temp: +125DEGC; Max Tol: +0.3nH; Min Oper Temp: -55DEGC; Min Tol: -0.3nH; Mounting Type: SMD; NOTE Status: PREFERRED; Packing Size: 10000; Packing Type: TAPE_&_REEL; Part Number: 03-06221; Part Type: INDUCTOR\CHIP\0402; Revision: R003; RoHS Status: ROHS_COMPLIANT; Rtd Current: 0.3A; WEIGHT: 0.001g
P6 = CONN_HEADER_2X6_P_S: CONNECTOR, HEADER, MALE, STRAIGHT, 2 ROW, 12 PINS, PITCH 2.54mm, SMD; ALT_SYMBOLS: SAMTEC_TSM10601LDVPL,SAMTEC_TSM10601LDVPM; AutoDoc File: http://notefied-dynamic-precision.com/DB/Apps/Desktop/Item/Object.aspx?id=95921; Budget Currency: USD; Budget Price: 1.08; Datasheet URL 1: http://www.samtec.com/documents/webfiles/cpdf/TSM-1XX-XX-XXX-XX-X-XXX-X-MKT.pdf; Datasheet URL 2: http://www.samtec.com/documents/webfiles/pdf/TSM.PDF; Definied Quality: INDUSTRIAL; Esd Level: N/A; FPLIST: SAMTEC_TSM10601LDVPN,SAMTEC_TSM10601LDVPL,SAMTEC_TSM10601LDVPM; Last Time Buy: N/A; Lead Time: 3; MPN Status: ACTIVE; MSL: N/A; MTBF: N/A; MTBF Standard: N/A; Manufacturer: SAMTEC; Max Oper Temp: +105DEGC; Min Oper Temp: -55DEGC; Mounting Type: SMD; NOTE Status: PREFERRED; No Of Pos: 12; No Of Rows: 2; Packing Size: 38; Packing Type: TUBE; Part Number: 06-03514; Part Type: CONNECTOR\HEADER; Pitch: 2.54mm; Revision: R002; RoHS Status: ROHS_COMPLIANT; WEIGHT: 0.92124g
R11 = RESISTOR: RESISTOR, THICK FILM, 3.3k, -5%/+5%, 0.063W, 50V, -55DEGC/+155DEGC, 0402, SMD; ALT_SYMBOLS: RESC1005X40L,RESC1005X40M; AutoDoc File: http://notefied-dynamic-precision.com/DB/Apps/Desktop/Item/Object.aspx?id=75727; Budget Currency: USD; Budget Price: 0.00244; Datasheet URL 1: N/A; Datasheet URL 2: N/A; Definied Quality: INDUSTRIAL; Esd Level: N/A; FPLIST: RESC1005X40N,RESC1005X40L,RESC1005X40M; Last Time Buy: N/A; Lead Time: N/A; LifeCycle Status: ACTIVE; MPN: RESISTOR_0402_3.3k_+/-5%_50V_0.063W_M_+/-200ppm; MPN Status: ACTIVE; MSL: N/A; MTBF: N/A; MTBF Standard: N/A; Manufacturer: MANUFACTURER SELECTION; Max Oper Temp: +155DEGC; Max TC: +200PPM/DEGC; Max Tol: +5%; Min Oper Temp: -55DEGC; Min TC: -200PPM/DEGC; Min Tol: -5%; Mounting Type: SMD; NOTE Status: PREFERRED; PCB Package: 0402; Packing Size: 10000; Packing Type: TAPE_&_REEL; Part Number: 01-11672; Part Type: RESISTOR\0402; Resistor Type: THICK FILM; Revision: R000; RoHS Status: ROHS_COMPLIANT; Rtd Power: 0.063W; Rtd Voltage: 50V; WEIGHT: N/A
R12 = RESISTOR: RESISTOR, THICK FILM, 47, -5%/+5%, 0.063W, 50V, -55DEGC/+155DEGC, 0402, SMD; ALT_SYMBOLS: RESC1005X40L,RESC1005X40M; AutoDoc File: http://notefied-dynamic-precision.com/DB/Apps/Desktop/Item/Object.aspx?id=75683; Budget Currency: USD; Budget Price: 0.00244; Datasheet URL 1: N/A; Datasheet URL 2: N/A; Definied Quality: INDUSTRIAL; Esd Level: N/A; FPLIST: RESC1005X40N,RESC1005X40L,RESC1005X40M; Last Time Buy: N/A; Lead Time: N/A; LifeCycle Status: ACTIVE; MPN: RESISTOR_0402_47_+/-5%_50V_0.063W_M_+/-200ppm; MPN Status: ACTIVE; MSL: N/A; MTBF: N/A; MTBF Standard: N/A; Manufacturer: MANUFACTURER SELECTION; Max Oper Temp: +155DEGC; Max TC: +200PPM/DEGC; Max Tol: +5%; Min Oper Temp: -55DEGC; Min TC: -200PPM/DEGC; Min Tol: -5%; Mounting Type: SMD; NOTE Status: PREFERRED; PCB Package: 0402; Packing Size: 10000; Packing Type: TAPE_&_REEL; Part Number: 01-11628; Part Type: RESISTOR\0402; Resistor Type: THICK FILM; Revision: R000; RoHS Status: ROHS_COMPLIANT; Rtd Power: 0.063W; Rtd Voltage: 50V; WEIGHT: N/A
R23-R25 = RESISTOR: RESISTOR, THICK FILM, 10k, -5%/+5%, 0.063W, 50V, -55DEGC/+155DEGC, 0402, SMD; ALT_SYMBOLS: RESC1005X40L,RESC1005X40M; AutoDoc File: http://notefied-dynamic-precision.com/DB/Apps/Desktop/Item/Object.aspx?id=75739; Budget Currency: USD; Budget Price: 0.00244; Datasheet URL 1: N/A; Datasheet URL 2: N/A; Definied Quality: INDUSTRIAL; Esd Level: N/A; FPLIST: RESC1005X40N,RESC1005X40L,RESC1005X40M; Last Time Buy: N/A; Lead Time: N/A; LifeCycle Status: ACTIVE; MPN: RESISTOR_0402_10k_+/-5%_50V_0.063W_M_+/-200ppm; MPN Status: ACTIVE; MSL: N/A; MTBF: N/A; MTBF Standard: N/A; Manufacturer: MANUFACTURER SELECTION; Max Oper Temp: +155DEGC; Max TC: +200PPM/DEGC; Max Tol: +5%; Min Oper Temp: -55DEGC; Min TC: -200PPM/DEGC; Min Tol: -5%; Mounting Type: SMD; NOTE Status: PREFERRED; PCB Package: 0402; Packing Size: 10000; Packing Type: TAPE_&_REEL; Part Number: 01-11684; Part Type: RESISTOR\0402; Resistor Type: THICK FILM; Revision: R000; RoHS Status: ROHS_COMPLIANT; Rtd Power: 0.063W; Rtd Voltage: 50V; WEIGHT: N/A
SC1 = SHIELD_COVER_BMIS-202: MECHANICAL, FRAME, SMD; AutoDoc File: http://notefied-dynamic-precision.com/DB/Apps/Desktop/Item/Object.aspx?id=90859; Budget Currency: EUR; Budget Price: 0.513; Datasheet URL 1: https://www.digikey.com/Web%20Export/Supplier%20Content/laird-emi-903/pdf/laired-catalog-essentials.pdf?redirected=1; Datasheet URL 2: http://lairdtech.thomasnet.com/item/board-level-shielding/standard-surface-mount-shields-two-piece/bmis-202; Definied Quality: MILITARY; Esd Level: N/A; FPLIST: MECH_BMIS202FN,; Last Time Buy: N/A; Lead Time: 4; MPN: BMI-S-202-F; MPN Status: ACTIVE; MSL: N/A; MTBF: N/A; MTBF Standard: N/A; Manufacturer: LAIRD; Max Oper Temp: +85DEGC; Min Oper Temp: -40DEGC; Mounting Type: SMD; NOTE Status: PREFERRED; Packing Size: 700; Packing Type: TAPE_&_REEL; Part Number: 13-00497; Part Type: MECHANIC\SHIELD; Revision: R001; RoHS Status: ROHS_COMPLIANT; WEIGHT: N/A
U2 = IC_RF_CC1190_QFN16: IC, ANALOG, 850-950MHz, RF FRONT END, 2V TO 3.7V, VQFN16, SMD; ALT_SYMBOLS: QFNFC65P400X400X100-17AL,QFNFC65P400X400X100-17AM; AutoDoc File: http://notefied-dynamic-precision.com/DB/Apps/Desktop/Item/Object.aspx?id=90713; Budget Currency: USD; Budget Price: 1.75; Datasheet URL 1: N/A; Datasheet URL 2: http://www.ti.com/lit/ds/symlink/cc1190.pdf; Definied Quality: INDUSTRIAL; Esd Level: HBM 1.5kV; FPLIST: QFNFC65P400X400X100-17AN,QFNFC65P400X400X100-17AL,QFNFC65P400X400X100-17AM; Frequency: 850MHz TO 950MHz; Last Time Buy: N/A; Lead Time: 10; MPN: CC1190RGVT; MPN Status: ACTIVE; MSL: 3; MTBF: 3.19*10^8; MTBF Standard: MTTF,CL=60%,Tu=55,Ea=0.7,Tt=125; Manufacturer: TEXAS INSTRUMENTS; Max Oper Temp: +85DEGC; Min Oper Temp: -40DEGC; Mounting Type: SMD; NOTE Status: PREFERRED; PCB Package: VQFN16; Packing Size: 250; Packing Type: TAPE_&_REEL; Part Number: 18-29008; Part Type: IC\ANALOG\RF\MODULATOR; Revision: R001; RoHS Status: ROHS_COMPLIANT; Rtd Voltage: 2V TO 3.7V; WEIGHT: 0.0397g

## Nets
3V3: C27.1 L4.1 ; also on sheet 1 3
GND: C26.1 C27.2 C28.2 C29.2 C30.2 C31.2 C32.2 C33.2 C37.1 C38.1 C39.1 C59.2 FL2.1(GND) FL2.3(GND) FL2.4(GND) FL2.6(GND) J3.M1 J3.M2 L11.2 P6.4 R11.1 SC1.1(GND) SC1.2(GND) SC1.3(GND) SC1.4(GND) SC1.5(GND) SC1.6(GND) SC1.7(GND) SC1.8(GND) U2.1(GND) U2.3(GND) U2.9(GND) U2.12(GND) U2.17(GND) ; also on sheet 1 3
VDD_CC1190: C28.1 C30.1 C31.1 C32.1 C33.1 L4.2 L5.2 L6.1 L7.1 P6.2 R12.2
CC112x_RF: FL2.5(OUT) ; also on sheet 3
HGM: R23.1 U2.6(HGM)
LNA_EN: R24.1 U2.7(LNA_EN)
LNA_EN_LP: P6.6 ; also on sheet 1
PA_EN: R25.1 U2.8(PA_EN)
PA_EN_LP: P6.10 ; also on sheet 1
RF_GPIO0: P6.12 ; also on sheet 1 3
RF_GPIO2: P6.8 ; also on sheet 1 3
N342853: L3.2 U2.10(LNA_OUT) U2.11(PA_IN)
N342874: C26.2 FL2.2(IN) L3.1
N343088: R11.2 U2.14(BIAS)
N343666: R12.1 U2.15(VDD_PA2)
N343673: L6.2 U2.16(VDD_PA1)
N343813: C29.1 L5.1 U2.13(VDD_LNA)
N344199: C35.1 L7.2 L13.1 U2.2(PA_OUT)
N344697: C34.2 C36.1 U2.4(TR_SW)
N344701: C34.1 U2.5(LNA_IN)
N344947: C35.2 C37.2 C60.1 L8.1 L9.1
N345002: C38.2 C60.2 L9.2 L10.1
N345235: C39.2 J3.1(IN) L10.2
N348306: A1.1(FEED/GND) C40.2 L11.1
N367241: P6.9 P6.11 R25.2
N367275: P6.5 P6.7 R24.2
N367294: P6.1 P6.3 R23.2
N398938: C36.2 L8.2
N399362: C59.1 L13.2
N401261: C40.1 J3.2(OUT)

Not connected (* = marked no-connect by the designer): FIDU1 1; FIDU2 1; FIDU3 1

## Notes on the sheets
sheet 2
- FL2 = B3588 for 915MHz band
  FL2 = B3725 for 868MHz band
  Refer to corresponding BOMs for part nos.
- C40 = 0 ohms for 915MHz band
  L11 =12nH for 915MHz band
  C40 = 3pF for 868MHz band
  L11 =6.8nH for 868MHz band
  Refer to corresponding BOMs for part nos.
- Don not Mount L13, C59 & C60 for 915MHz Design
  L13, C59 & C60 for 868MHz Design only.
  Refer to corresponding BOMs for values
- Default Positions (For LaunchPad):
  Mount Jumper in between 9 & 10
  Mount Jumper in between 5 & 6
  Mount Jumper in between 1 & 2
- PAEN - Connect 11 & 12 to control from SmartRFStudio
  LNAEN - Connect 7 & 8 to control from SmartRFStudio
  Set GPIO2=0x33 & GPIO0 = 0x73 in SRS to set CC1190 in Tx
  Set GPIO2=0x73 & GPIO0 = 0x33 in SRS to set CC1190 in Rx
- PAEN - Connect 9 & 10 to control from LaunchPad
  LNAEN - Connect 5 & 6 to control from LaunchPad
- HGM - Connect 1 & 2 to set for High Gain mode
  HGM - Connect 3 & 4 to set for Low Gain mode
